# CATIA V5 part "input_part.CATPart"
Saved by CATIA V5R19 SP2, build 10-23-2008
Part number: input_part
Bounding box of the stored display mesh (mm): x -30 to 30, y -30 to 30, z 0 to 40
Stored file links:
  D:\Catia\Makra\test_maker\input_part.CATPart
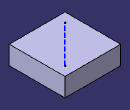
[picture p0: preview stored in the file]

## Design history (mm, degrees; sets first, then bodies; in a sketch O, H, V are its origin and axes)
AxisSystem1: origin (0, 0, 0), X (1, 0, 0), Y (0, 1, 0), Z (0, 0, 1)
Set1 "Geometrical Set.1"
  Point1: (0, 0, 0), in AxisSystem1
  Line1: type PtDir, RefPoint Point1, Direction xy-plane, Start 0, End 40
Body1 (main body)
  Sketch1 on xy-plane, origin (0, 0, 0), H (1, 0, 0), V (0, 1, 0)
    line L1 (-30, 30) -> (30, 30)
    line L2 (30, 30) -> (30, -30)
    line L3 (30, -30) -> (-30, -30)
    line L4 (-30, -30) -> (-30, 30)
    horizontal: L1 H, L3 H
    vertical: L2 V, L4 V
  Pad1: profile Sketch1, direction (0, 0, 1), length 20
